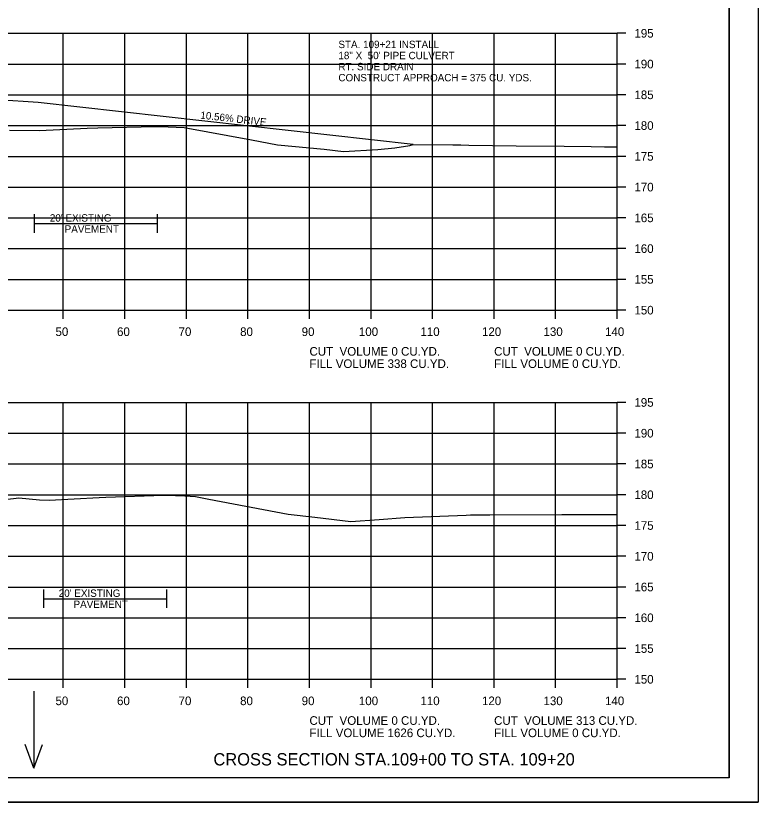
# Model space of a CAD drawing. Extents: x 915787 to 919910, y 133456 to 136717.
# Drawn here: x 916456.2 to 916576.9, y 134096 to 134223.9 of the extents above; entities that cross this region are included whole.
import ezdxf

# ---------------------------------------------------------------- set-up
doc = ezdxf.new("R2010")
doc.units = 0
for name, color, linetype in [('R_Axis', 7, 'Continuous'), ('R_Axis Annot', 7, 'Continuous'), ('R_Border', 7, 'Continuous'), ('R_Border Notes', 7, 'Continuous'), ('R_Draft', 7, 'Continuous'), ('R_Drive', 7, 'Continuous'), ('R_Exist Surface', 7, 'Continuous'), ('R_Exist Surface Annot', 7, 'Continuous'), ('R_Grid', 7, 'Continuous'), ('R_No Plot', 7, 'Continuous'), ('R_Water Annot', 7, 'Continuous')]:
    doc.layers.add(name, color=color, linetype=linetype)

msp = doc.modelspace()

# ---------------------------------------------------------------- linework, layer by layer
at = {"layer": 'R_Axis'}
for p, q in [((916553.98, 134176.03), (916553.98, 134221.03)), ((916555.38, 134221.03), (916553.98, 134221.03)), ((916555.38, 134216.03), (916553.98, 134216.03)), ((916555.38, 134211.03), (916553.98, 134211.03)), ((916555.38, 134206.03), (916553.98, 134206.03)), ((916555.38, 134201.03), (916553.98, 134201.03)), ((916555.38, 134196.03), (916553.98, 134196.03)), ((916555.38, 134191.03), (916553.98, 134191.03)), ((916555.38, 134186.03), (916553.98, 134186.03)), ((916555.38, 134181.03), (916553.98, 134181.03)), ((916273.98, 134176.03), (916553.98, 134176.03)), ((916463.98, 134174.63), (916463.98, 134176.03)), ((916473.98, 134174.63), (916473.98, 134176.03)), ((916483.98, 134174.63), (916483.98, 134176.03)), ((916493.98, 134174.63), (916493.98, 134176.03)), ((916503.98, 134174.63), (916503.98, 134176.03)), ((916513.98, 134174.63), (916513.98, 134176.03)), ((916523.98, 134174.63), (916523.98, 134176.03)), ((916533.98, 134174.63), (916533.98, 134176.03)), ((916543.98, 134174.63), (916543.98, 134176.03)), ((916553.98, 134174.63), (916553.98, 134176.03)), ((916555.38, 134176.03), (916553.98, 134176.03)), ((916553.98, 134116.03), (916553.98, 134161.03)), ((916555.38, 134161.03), (916553.98, 134161.03)), ((916555.38, 134156.03), (916553.98, 134156.03)), ((916555.38, 134151.03), (916553.98, 134151.03)), ((916555.38, 134146.03), (916553.98, 134146.03)), ((916555.38, 134141.03), (916553.98, 134141.03)), ((916555.38, 134136.03), (916553.98, 134136.03)), ((916555.38, 134131.03), (916553.98, 134131.03)), ((916555.38, 134126.03), (916553.98, 134126.03)), ((916555.38, 134121.03), (916553.98, 134121.03)), ((916273.98, 134116.03), (916553.98, 134116.03)), ((916463.98, 134114.63), (916463.98, 134116.03)), ((916473.98, 134114.63), (916473.98, 134116.03)), ((916483.98, 134114.63), (916483.98, 134116.03)), ((916493.98, 134114.63), (916493.98, 134116.03)), ((916503.98, 134114.63), (916503.98, 134116.03)), ((916513.98, 134114.63), (916513.98, 134116.03)), ((916523.98, 134114.63), (916523.98, 134116.03)), ((916533.98, 134114.63), (916533.98, 134116.03)), ((916543.98, 134114.63), (916543.98, 134116.03)), ((916553.98, 134114.63), (916553.98, 134116.03)), ((916555.38, 134116.03), (916553.98, 134116.03))]:
    msp.add_line(p, q, dxfattribs=at)
at = {"layer": 'R_Border'}
for q in [(916572.16, 134305.49), (916255.98, 134100.03)]:
    msp.add_line((916572.16, 134100.03), q, dxfattribs=at)
at = {"layer": 'R_Drive'}
for p, q in [((916459.91, 134209.76), (916449.93, 134210.43)), ((916520.83, 134202.93), (916459.91, 134209.76))]:
    msp.add_line(p, q, dxfattribs=at)
at = {"layer": 'R_Exist Surface'}
for points in [[(916455.26, 134205.27), (916460.11, 134205.21), (916467.87, 134205.6), (916469.59, 134205.68), (916478.95, 134205.89), (916479.42, 134205.89), (916479.74, 134205.88), (916483.63, 134205.71), (916494.56, 134203.7), (916498.77, 134202.92), (916506.36, 134202.19), (916509.52, 134201.82), (916515.07, 134202.16), (916517.87, 134202.39), (916520.28, 134202.8), (916520.83, 134202.93), (916527.3, 134202.89), (916528.6, 134202.88), (916529.85, 134202.87), (916537.55, 134202.76), (916545.35, 134202.67), (916549.74, 134202.63), (916551.94, 134202.58), (916553.98, 134202.56)], [(916452.69, 134145.06), (916456.75, 134145.51), (916460.1, 134145.2), (916461.7, 134145.12), (916469.81, 134145.58), (916470.91, 134145.63), (916480.24, 134145.97), (916480.9, 134145.98), (916482.23, 134145.91), (916483.73, 134145.85), (916485.47, 134145.74), (916487.65, 134145.31), (916500.53, 134142.89), (916504.83, 134142.36), (916510.72, 134141.67), (916515.29, 134142.03), (916519.5, 134142.33), (916529.43, 134142.7), (916530.13, 134142.77), (916531.43, 134142.75), (916533.31, 134142.75), (916545, 134142.81), (916553.98, 134142.82)]]:
    msp.add_lwpolyline(points, dxfattribs=at)
at = {"layer": 'R_Exist Surface Annot'}
for p, q in [((916459.26, 134191.62), (916459.26, 134188.62)), ((916479.25, 134191.62), (916479.25, 134188.62)), ((916459.26, 134190.12), (916479.25, 134190.12)), ((916460.75, 134130.63), (916460.75, 134127.63)), ((916480.74, 134130.63), (916480.74, 134127.63)), ((916460.75, 134129.13), (916480.74, 134129.13))]:
    msp.add_line(p, q, dxfattribs=at)
at = {"layer": 'R_Grid'}
for p, q in [((916273.98, 134221.03), (916553.98, 134221.03)), ((916463.98, 134176.03), (916463.98, 134221.03)), ((916473.98, 134176.03), (916473.98, 134221.03)), ((916483.98, 134176.03), (916483.98, 134221.03)), ((916493.98, 134176.03), (916493.98, 134221.03)), ((916503.98, 134176.03), (916503.98, 134221.03)), ((916513.98, 134176.03), (916513.98, 134221.03)), ((916523.98, 134176.03), (916523.98, 134221.03)), ((916533.98, 134176.03), (916533.98, 134221.03)), ((916543.98, 134176.03), (916543.98, 134221.03)), ((916553.98, 134176.03), (916553.98, 134221.03)), ((916273.98, 134216.03), (916553.98, 134216.03)), ((916273.98, 134211.03), (916553.98, 134211.03)), ((916273.98, 134206.03), (916553.98, 134206.03)), ((916273.98, 134201.03), (916553.98, 134201.03)), ((916273.98, 134196.03), (916553.98, 134196.03)), ((916273.98, 134191.03), (916553.98, 134191.03)), ((916273.98, 134186.03), (916553.98, 134186.03)), ((916273.98, 134181.03), (916553.98, 134181.03)), ((916273.98, 134176.03), (916553.98, 134176.03)), ((916273.98, 134161.03), (916553.98, 134161.03)), ((916463.98, 134116.03), (916463.98, 134161.03)), ((916473.98, 134116.03), (916473.98, 134161.03)), ((916483.98, 134116.03), (916483.98, 134161.03)), ((916493.98, 134116.03), (916493.98, 134161.03)), ((916503.98, 134116.03), (916503.98, 134161.03)), ((916513.98, 134116.03), (916513.98, 134161.03)), ((916523.98, 134116.03), (916523.98, 134161.03)), ((916533.98, 134116.03), (916533.98, 134161.03)), ((916543.98, 134116.03), (916543.98, 134161.03)), ((916553.98, 134116.03), (916553.98, 134161.03)), ((916273.98, 134156.03), (916553.98, 134156.03)), ((916273.98, 134151.03), (916553.98, 134151.03)), ((916273.98, 134146.03), (916553.98, 134146.03)), ((916273.98, 134141.03), (916553.98, 134141.03)), ((916273.98, 134136.03), (916553.98, 134136.03)), ((916273.98, 134131.03), (916553.98, 134131.03)), ((916273.98, 134126.03), (916553.98, 134126.03)), ((916273.98, 134121.03), (916553.98, 134121.03)), ((916273.98, 134116.03), (916553.98, 134116.03))]:
    msp.add_line(p, q, dxfattribs=at)
at = {"layer": 'R_No Plot'}
msp.add_line((916243.57, 134096.05), (916576.91, 134096.05), dxfattribs=at)
for points in [[(916243.57, 134309.38), (916576.91, 134309.38), (916576.91, 134096.05), (916243.57, 134096.05)], [(916489.9, 134305.49), (916489.9, 134295.61), (916525.63, 134295.61), (916525.63, 134292.69), (916548.83, 134292.69), (916548.83, 134269.47), (916572.16, 134269.47), (916572.16, 134100.03), (916255.98, 134100.03), (916255.98, 134305.49)]]:
    msp.add_lwpolyline(points, close=True, dxfattribs=at)
at = {"layer": 'R_Water Annot'}
for p, q in [((916459.18, 134114.13), (916459.18, 134101.57)), ((916459.18, 134101.57), (916457.78, 134105.41)), ((916459.18, 134101.57), (916460.58, 134105.41))]:
    msp.add_line(p, q, dxfattribs=at)

# ---------------------------------------------------------------- texts
at = {"layer": 'R_Axis Annot'}
for s, p in [('195', (916556.78, 134220.33)), ('190', (916556.78, 134215.33)), ('185', (916556.78, 134210.33)), ('180', (916556.78, 134205.33)), ('175', (916556.78, 134200.33)), ('170', (916556.78, 134195.33)), ('165', (916556.78, 134190.33)), ('160', (916556.78, 134185.33)), ('155', (916556.78, 134180.33)), ('150', (916556.78, 134175.33)), ('50', (916462.71, 134171.83)), ('60', (916472.71, 134171.83)), ('70', (916482.71, 134171.83)), ('80', (916492.71, 134171.83)), ('90', (916502.71, 134171.83)), ('100', (916512.01, 134171.83)), ('110', (916522.01, 134171.83)), ('120', (916532.01, 134171.83)), ('130', (916542.01, 134171.83)), ('140', (916552.01, 134171.83)), ('195', (916556.78, 134160.33)), ('190', (916556.78, 134155.33)), ('185', (916556.78, 134150.33)), ('180', (916556.78, 134145.33)), ('175', (916556.78, 134140.33)), ('170', (916556.78, 134135.33)), ('165', (916556.78, 134130.33)), ('160', (916556.78, 134125.33)), ('155', (916556.78, 134120.33)), ('150', (916556.78, 134115.33)), ('50', (916462.71, 134111.83)), ('60', (916472.71, 134111.83)), ('70', (916482.71, 134111.83)), ('80', (916492.71, 134111.83)), ('90', (916502.71, 134111.83)), ('100', (916512.01, 134111.83)), ('110', (916522.01, 134111.83)), ('120', (916532.01, 134111.83)), ('130', (916542.01, 134111.83)), ('140', (916552.01, 134111.83))]:
    msp.add_text(s, height=1.4, dxfattribs=at).set_placement(p)
at = {"layer": 'R_Border Notes'}
for s, p in [('CUT  VOLUME 0 CU.YD.', (916503.98, 134168.63)), ('CUT  VOLUME 0 CU.YD.', (916533.98, 134168.63)), ('FILL VOLUME 338 CU.YD.', (916503.98, 134166.63)), ('FILL VOLUME 0 CU.YD.', (916533.98, 134166.63)), ('CUT  VOLUME 0 CU.YD.', (916503.98, 134108.63)), ('CUT  VOLUME 313 CU.YD.', (916533.98, 134108.63)), ('FILL VOLUME 1626 CU.YD.', (916503.98, 134106.63)), ('FILL VOLUME 0 CU.YD.', (916533.98, 134106.63))]:
    msp.add_text(s, height=1.4, dxfattribs=at).set_placement(p)
at = {"layer": 'R_Draft'}
msp.add_text('CROSS SECTION STA.109+00 TO STA. 109+20', height=2, dxfattribs=at).set_placement((916488.37, 134102.03))
at = {"layer": 'R_Drive'}
msp.add_text('10.56% DRIVE', height=1.2, rotation=353.6072, dxfattribs=at).set_placement((916486.2, 134207.17))
at = {"layer": 'R_Exist Surface Annot'}
for s, p in [("20' EXISTING", (916461.79, 134190.42)), ('PAVEMENT', (916464.2, 134188.62)), ("20' EXISTING", (916463.23, 134129.43)), ('PAVEMENT', (916465.64, 134127.63))]:
    msp.add_text(s, height=1.2, dxfattribs=at).set_placement(p)
at = {"layer": 'R_Water Annot'}
for s, p in [('STA. 109+21 INSTALL', (916508.68, 134218.62)), ('18" X  50\' PIPE CULVERT', (916508.68, 134216.82)), ('RT. SIDE DRAIN', (916508.68, 134215.02)), ('CONSTRUCT APPROACH = 375 CU. YDS.', (916508.68, 134213.22))]:
    msp.add_text(s, height=1.2, dxfattribs=at).set_placement(p)

doc.saveas('drawing.dxf')
